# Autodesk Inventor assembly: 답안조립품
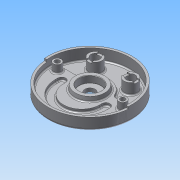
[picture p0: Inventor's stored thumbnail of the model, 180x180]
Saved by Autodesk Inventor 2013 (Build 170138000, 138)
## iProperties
Created: 2015-04
Part Number: 답안조립품
Document SubType Name: Assembly
Designer: Administrator
Author: Administrator
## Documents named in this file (2)
- C:\Users\Administrator\Desktop\450406V1001\답안조립품.iam
- C:\Users\Administrator\Desktop\450406V1001\본체.ipt
